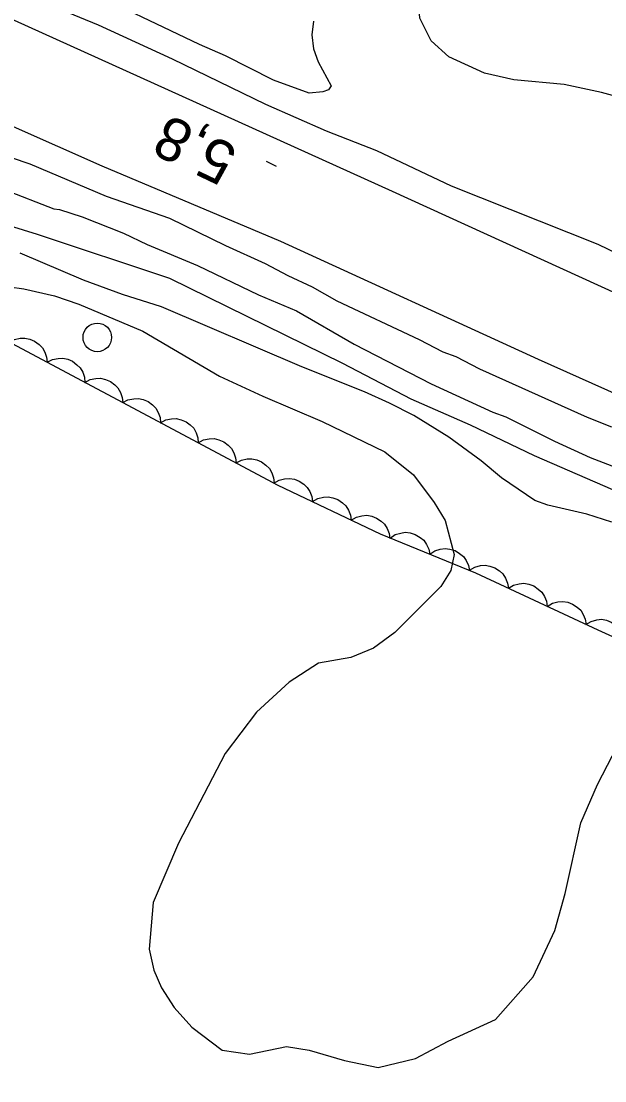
# Model space of a CAD drawing. Extents: x 282461 to 284471, y 5554090 to 5557646.
# Drawn here: x 283939.2 to 283980, y 5554771.5 to 5554845.7 of the extents above; entities that cross this region are included whole.
import ezdxf

# ---------------------------------------------------------------- set-up
doc = ezdxf.new("R2010")
doc.units = 0
for name, color, linetype in [('Niveau 1', 7, 'Continuous'), ('Niveau 2', 7, 'Continuous'), ('Niveau 21', 7, 'Continuous'), ('Niveau 3', 7, 'Continuous'), ('Niveau 36', 7, 'Continuous'), ('Niveau 4', 7, 'Continuous'), ('Niveau 44', 7, 'Continuous')]:
    doc.layers.add(name, color=color, linetype=linetype)

msp = doc.modelspace()

# ---------------------------------------------------------------- linework, layer by layer
at = {"layer": 'Niveau 1'}
for points in [[(283895.94, 5554867.5), (283897.76, 5554866.71), (283898.61, 5554866.26), (283899.52, 5554865.92), (283901.96, 5554864.72), (283903.66, 5554863.99), (283911.27, 5554860.18), (283914.11, 5554858.99), (283915.87, 5554858.37), (283918.09, 5554857.35), (283919.9, 5554856.67), (283932.17, 5554851.22), (283938.75, 5554848.16), (283939.43, 5554847.76), (283941.99, 5554846.57), (283944.6, 5554845.49), (283949.76, 5554843.11), (283956.29, 5554839.94), (283960.54, 5554838.06), (283964.06, 5554836.7), (283969.28, 5554834.21), (283979.55, 5554830.13), (283986.92, 5554826.56)], [(283981.85, 5554840.18), (283979.81, 5554840.74), (283977.19, 5554841.31), (283973.67, 5554841.65), (283971.62, 5554842.11), (283969.13, 5554843.24), (283967.88, 5554844.37), (283967.09, 5554845.96), (283966.99, 5554847.55), (283968.02, 5554848.9), (283969.85, 5554850.15), (283972.01, 5554851.39), (283973.73, 5554852.64), (283976.46, 5554854.33), (283978.86, 5554855.69), (283982.06, 5554858.86)], [(283916.66, 5554846.19), (283922.45, 5554843.41), (283923.3, 5554843.07), (283929.6, 5554839.95), (283932.22, 5554838.76), (283933.07, 5554838.25), (283933.98, 5554837.91), (283934.77, 5554837.46), (283939.82, 5554835.75), (283945.16, 5554833.49), (283949.59, 5554831.95), (283953.5, 5554830.03), (283956.28, 5554828.78), (283957.87, 5554827.93), (283959.57, 5554827.14), (283961.28, 5554826.17), (283967.06, 5554823.45), (283968.71, 5554822.6), (283969.62, 5554822.26), (283971.26, 5554821.41), (283978.81, 5554818.01), (283980.51, 5554817.33)], [(283910.08, 5554771.4), (283911.49, 5554775.1), (283912.42, 5554777), (283914.28, 5554780.24), (283915.81, 5554784.06), (283917.1, 5554787.65), (283918.74, 5554790.89), (283922.25, 5554799.19), (283925.08, 5554806.93), (283926.48, 5554809.28), (283927.98, 5554811.51), (283930.99, 5554816.31), (283934.12, 5554821.11), (283935.17, 5554823.47), (283935.76, 5554825.38), (283936.23, 5554826.27), (283937.37, 5554826.93), (283938.39, 5554827.14), (283939.4, 5554827.01), (283941.54, 5554826.52)], [(283941.54, 5554826.52), (283943.23, 5554825.92), (283947.72, 5554824.04), (283953.09, 5554820.89), (283956.12, 5554819.48), (283960.27, 5554817.71), (283964.64, 5554815.6), (283966.65, 5554813.99), (283968.09, 5554812.04), (283968.86, 5554810.79), (283969.5, 5554808.4), (283969.26, 5554807.28), (283968.56, 5554806.16), (283965.35, 5554802.94), (283963.86, 5554801.84), (283962.27, 5554801.19), (283960.01, 5554800.78), (283957.95, 5554799.46), (283955.66, 5554797.35), (283953.47, 5554794.46), (283950.21, 5554788.19), (283948.45, 5554784.04), (283948.17, 5554780.77), (283948.49, 5554779.3), (283949.03, 5554778.05), (283949.92, 5554776.68), (283951.14, 5554775.3), (283953.26, 5554773.68), (283955.17, 5554773.42), (283957.78, 5554773.94), (283959.36, 5554773.69), (283961.83, 5554772.97), (283964.19, 5554772.48), (283966.8, 5554773.11), (283969.08, 5554774.31), (283972.38, 5554775.83), (283975.02, 5554778.83), (283976.54, 5554782.08), (283977.26, 5554784.66), (283978.36, 5554789.61), (283979.53, 5554792.3), (283981.24, 5554795.64)]]:
    msp.add_lwpolyline(points, dxfattribs=at)
at = {"layer": 'Niveau 2'}
for points in [[(283959.66, 5554845.75), (283959.54, 5554844.78), (283959.65, 5554843.82), (283959.98, 5554842.91), (283960.89, 5554841.21), (283960.71, 5554840.93), (283960.31, 5554840.81), (283959.35, 5554840.7), (283956.85, 5554841.61), (283953.5, 5554843.31), (283951.68, 5554844.11), (283943.16, 5554848.19)], [(283924.83, 5554838.79), (283926.42, 5554837.83), (283929.04, 5554836.75), (283929.95, 5554836.47), (283930.8, 5554836.07), (283932.5, 5554835.45), (283933.47, 5554835.22), (283935.23, 5554834.65), (283938.02, 5554833.97), (283941.48, 5554832.61), (283941.88, 5554832.55), (283943.47, 5554832.04), (283946.37, 5554830.9), (283948.02, 5554830.11), (283951.54, 5554828.63), (283955.8, 5554826.59), (283958.47, 5554825.46), (283962.5, 5554823.13), (283967.89, 5554820.35), (283972.21, 5554818.37), (283973.11, 5554818.03), (283976.52, 5554816.33), (283979.02, 5554815.19), (283982.54, 5554813.83)], [(283980.53, 5554810.66), (283978.77, 5554811.23), (283976.04, 5554811.85), (283975.13, 5554812.19), (283972.81, 5554813.78), (283971.39, 5554814.97), (283969.12, 5554816.61), (283966.68, 5554818.14), (283964.98, 5554818.99), (283963.22, 5554819.79), (283958.85, 5554821.55), (283949.02, 5554825.75), (283946.29, 5554826.6), (283943.57, 5554827.62), (283939.13, 5554829.49)]]:
    msp.add_lwpolyline(points, dxfattribs=at)
at = {"layer": 'Niveau 21'}
for points in [[(283896.54, 5554865.24), (283906.59, 5554860.53), (283913.91, 5554857.24), (283921.63, 5554853.44), (283936.73, 5554846.7), (283965.15, 5554833.84), (284014.91, 5554811.14), (284025.97, 5554805.86)], [(283894.01, 5554859.02), (283904.79, 5554853.98), (283912.17, 5554850.4), (283922.9, 5554845.36), (283944.86, 5554835.61), (283957.34, 5554830.35), (283975.37, 5554822.08), (283983.99, 5554818.23), (284000.08, 5554810.69), (284009.04, 5554806.84), (284024.99, 5554799.62)]]:
    msp.add_lwpolyline(points, dxfattribs=at)
at = {"layer": 'Niveau 3'}
msp.add_line((283957.08, 5554835.57), (283956.36, 5554835.92), dxfattribs=at)
at = {"layer": 'Niveau 36'}
msp.add_circle((283944.534, 5554823.603), 1, dxfattribs=at)
at = {"layer": 'Niveau 4'}
msp.add_lwpolyline([(284011.88, 5554799.19), (284006.96, 5554801.33), (284004.33, 5554802.58), (283999.23, 5554804.74), (283994.41, 5554806.94), (283975.11, 5554815.3), (283970.63, 5554817.46), (283966.48, 5554819.28), (283961.71, 5554821.77), (283949.61, 5554827.73), (283940.34, 5554830.8), (283934.37, 5554832.66), (283930.62, 5554833.73), (283928.8, 5554834.06), (283926.46, 5554833.89), (283925.09, 5554833.7)], dxfattribs=at)
at = {"layer": 'Niveau 44'}
for points in [[(283932.55, 5554826.37), (283957.17, 5554813.26), (283964.32, 5554809.84), (283971, 5554807.11), (283979.55, 5554803.12), (283992.32, 5554797.31)], [(283938.38, 5554823.27), (283938.74, 5554823.46), (283939.14, 5554823.54), (283939.47, 5554823.56), (283939.81, 5554823.48), (283940.15, 5554823.33), (283940.46, 5554823.1), (283940.69, 5554822.88), (283940.86, 5554822.57), (283940.98, 5554822.22), (283941.02, 5554821.86)], [(283941.02, 5554821.86), (283941.39, 5554822.05), (283941.79, 5554822.13), (283942.12, 5554822.15), (283942.46, 5554822.07), (283942.8, 5554821.93), (283943.1, 5554821.69), (283943.34, 5554821.47), (283943.51, 5554821.16), (283943.63, 5554820.81), (283943.67, 5554820.45)], [(283943.67, 5554820.45), (283944.04, 5554820.65), (283944.43, 5554820.72), (283944.76, 5554820.74), (283945.11, 5554820.66), (283945.45, 5554820.52), (283945.75, 5554820.28), (283945.98, 5554820.06), (283946.15, 5554819.75), (283946.27, 5554819.4), (283946.31, 5554819.04)], [(283946.31, 5554819.04), (283946.68, 5554819.24), (283947.08, 5554819.31), (283947.41, 5554819.33), (283947.75, 5554819.25), (283948.09, 5554819.11), (283948.39, 5554818.87), (283948.63, 5554818.65), (283948.8, 5554818.34), (283948.92, 5554817.99), (283948.96, 5554817.63)], [(283948.96, 5554817.63), (283949.33, 5554817.83), (283949.73, 5554817.91), (283950.06, 5554817.92), (283950.4, 5554817.84), (283950.74, 5554817.7), (283951.04, 5554817.47), (283951.28, 5554817.24), (283951.44, 5554816.93), (283951.57, 5554816.58), (283951.6, 5554816.22)], [(283951.6, 5554816.22), (283951.97, 5554816.42), (283952.37, 5554816.5), (283952.7, 5554816.52), (283953.04, 5554816.44), (283953.38, 5554816.29), (283953.69, 5554816.06), (283953.92, 5554815.83), (283954.09, 5554815.52), (283954.21, 5554815.17), (283954.25, 5554814.81)], [(283954.25, 5554814.81), (283954.62, 5554815.01), (283955.02, 5554815.09), (283955.35, 5554815.11), (283955.69, 5554815.03), (283956.03, 5554814.88), (283956.33, 5554814.65), (283956.57, 5554814.42), (283956.74, 5554814.11), (283956.86, 5554813.76), (283956.9, 5554813.41)], [(283956.89, 5554813.39), (283957.25, 5554813.61), (283957.64, 5554813.7), (283957.97, 5554813.73), (283958.32, 5554813.67), (283958.66, 5554813.54), (283958.98, 5554813.32), (283959.22, 5554813.1), (283959.4, 5554812.8), (283959.54, 5554812.46), (283959.59, 5554812.1)], [(283959.59, 5554812.1), (283959.95, 5554812.31), (283960.35, 5554812.41), (283960.68, 5554812.44), (283961.02, 5554812.37), (283961.37, 5554812.24), (283961.68, 5554812.02), (283961.93, 5554811.81), (283962.11, 5554811.51), (283962.24, 5554811.16), (283962.3, 5554810.81)], [(283962.3, 5554810.81), (283962.66, 5554811.02), (283963.05, 5554811.11), (283963.38, 5554811.15), (283963.73, 5554811.08), (283964.07, 5554810.95), (283964.39, 5554810.73), (283964.63, 5554810.52), (283964.81, 5554810.21), (283964.95, 5554809.87), (283965, 5554809.51)], [(283965.02, 5554809.55), (283965.37, 5554809.79), (283965.76, 5554809.9), (283966.08, 5554809.96), (283966.43, 5554809.91), (283966.78, 5554809.8), (283967.11, 5554809.6), (283967.37, 5554809.4), (283967.56, 5554809.11), (283967.72, 5554808.77), (283967.79, 5554808.42)], [(283967.79, 5554808.42), (283968.14, 5554808.65), (283968.53, 5554808.77), (283968.86, 5554808.82), (283969.2, 5554808.78), (283969.56, 5554808.67), (283969.88, 5554808.46), (283970.14, 5554808.26), (283970.34, 5554807.97), (283970.49, 5554807.64), (283970.57, 5554807.29)], [(283970.58, 5554807.31), (283970.94, 5554807.52), (283971.33, 5554807.62), (283971.66, 5554807.66), (283972, 5554807.59), (283972.35, 5554807.47), (283972.67, 5554807.25), (283972.91, 5554807.04), (283973.1, 5554806.74), (283973.24, 5554806.39), (283973.29, 5554806.04)], [(283973.29, 5554806.04), (283973.65, 5554806.25), (283974.05, 5554806.35), (283974.37, 5554806.39), (283974.72, 5554806.33), (283975.07, 5554806.2), (283975.38, 5554805.98), (283975.63, 5554805.77), (283975.81, 5554805.47), (283975.95, 5554805.13), (283976.01, 5554804.77)], [(283976.01, 5554804.77), (283976.37, 5554804.99), (283976.76, 5554805.08), (283977.09, 5554805.12), (283977.44, 5554805.06), (283977.78, 5554804.93), (283978.1, 5554804.71), (283978.35, 5554804.5), (283978.53, 5554804.2), (283978.67, 5554803.86), (283978.73, 5554803.5)], [(283978.72, 5554803.5), (283979.08, 5554803.71), (283979.47, 5554803.82), (283979.8, 5554803.86), (283980.15, 5554803.8), (283980.49, 5554803.67), (283980.81, 5554803.46), (283981.06, 5554803.25), (283981.25, 5554802.95), (283981.39, 5554802.61), (283981.45, 5554802.25)]]:
    msp.add_lwpolyline(points, dxfattribs=at)

# ---------------------------------------------------------------- texts
at = {"layer": 'Niveau 3'}
msp.add_text('5,8  ', height=3, rotation=154.36645, dxfattribs=at).set_placement((283954.5, 5554836.85))

doc.saveas('drawing.dxf')
